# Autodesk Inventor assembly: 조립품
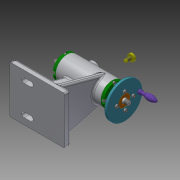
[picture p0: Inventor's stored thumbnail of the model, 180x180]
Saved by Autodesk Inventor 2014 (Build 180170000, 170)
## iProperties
Created: 2019-10
Part Number: 조립품
Document SubType Name: Assembly
Designer: kh
Author: kh
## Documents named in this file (16)
- C:\Users\kh\Desktop\491004V1003\조립품.iam
- C:\Users\kh\Desktop\491004V1003\본체.ipt
- C:\Users\kh\Desktop\491004V1003\나사축.ipt
- C:\Users\kh\Desktop\491004V1003\멈춤나사 M3.ipt
- C:\Users\kh\Desktop\491004V1003\센터.ipt
- C:\Users\kh\Desktop\491004V1003\센터홀더.ipt
- C:\Users\kh\Desktop\491004V1003\중공축.ipt
- C:\Users\kh\Desktop\491004V1003\부시.ipt
- C:\Users\kh\Desktop\491004V1003\커버.ipt
- C:\Users\kh\Desktop\491004V1003\키 4 x 4 x 10.ipt
- C:\Users\kh\Desktop\491004V1003\플랜지.ipt
- C:\Users\kh\Desktop\491004V1003\돌림판.ipt
- C:\Users\kh\Desktop\491004V1003\핸들.ipt
- C:\Users\kh\Desktop\491004V1003\볼트 M3.ipt
- C:\Users\kh\Desktop\491004V1003\슬리브.ipt
- C:\Users\kh\Desktop\491004V1003\나사.ipt
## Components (2 placed, 2 different names)
1. 플랜지:1 — Insert:4, Mate:2, Insert:5, Mate:3, Mate:4
2. 핸들:1 — Insert:6
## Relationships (6: Insert 3, Mate 3)
- Insert:4: 플랜지:1
- Mate:2: 플랜지:1
- Insert:5: 플랜지:1
- Mate:3: 플랜지:1
- Mate:4: 플랜지:1
- Insert:6: 핸들:1
